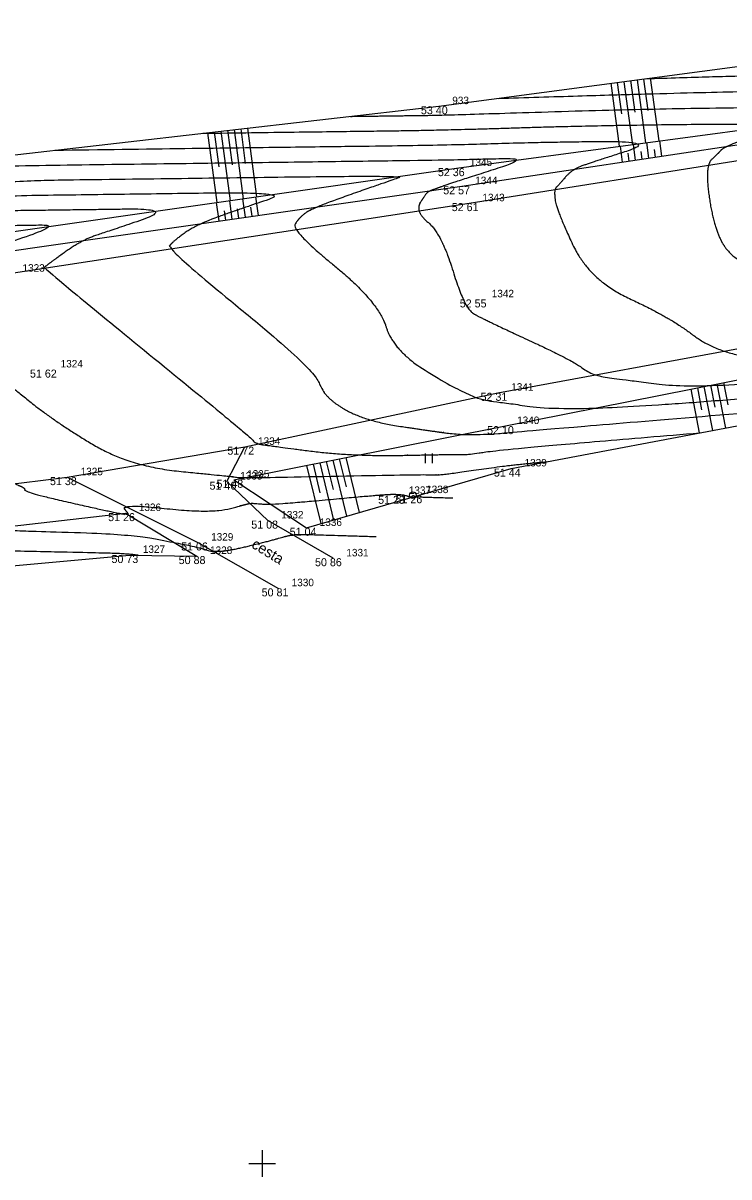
# Model space of a CAD drawing. Extents: x -704017 to -701500, y -1008977 to -1008450.
# Drawn here: x -703008.96 to -702982.5, y -1008850.5 to -1008807.25 of the extents above; entities that cross this region are included whole.
import ezdxf

# ---------------------------------------------------------------- set-up
doc = ezdxf.new("R2010")
doc.units = 0
for name, color, linetype in [('Z_body', 7, 'Continuous'), ('Z_body_cisla', 7, 'Continuous'), ('Z_body_vysky', 7, 'Continuous'), ('Z_cesty', 7, 'Continuous'), ('Z_hekt_sit', 7, 'Continuous'), ('Z_komunikace', 7, 'Continuous'), ('Z_popis', 7, 'Continuous'), ('Z_sloupky', 7, 'Continuous'), ('Z_teren_hrany_paty', 7, 'Continuous'), ('Z_vrstevnice_hlavni', 7, 'Continuous'), ('Z_vrstevnice_vedlejsi', 7, 'Continuous')]:
    doc.layers.add(name, color=color, linetype=linetype)

# ---------------------------------------------------------------- blocks, each defined once
blk = doc.blocks.new('POINT_DISPLAY')
blk.add_line((0, 0), (0, 0))
blk = doc.blocks.new('Z306')
for p, q in [((-0.13, 0.17), (-0.13, -0.2)), ((0.13, 0.17), (0.13, -0.2))]:
    blk.add_line(p, q)
blk = doc.blocks.new('Z15')
blk.add_circle((0, 0), 0.125)

msp = doc.modelspace()

# ---------------------------------------------------------------- linework, layer by layer
at = {"layer": 'Z_cesty'}
for p, q in [((-703001.32, -1008824.44), (-703000.65, -1008823.13)), ((-703007.3, -1008824.27), (-703002.41, -1008826.72)), ((-702999.78, -1008825.9), (-703001.32, -1008824.44)), ((-702997.34, -1008827.31), (-702999.78, -1008825.9)), ((-703002.41, -1008826.72), (-702999.39, -1008828.44))]:
    msp.add_line(p, q, dxfattribs=at)
at = {"layer": 'Z_hekt_sit'}
for p, q in [((-703000, -1008849.5), (-703000, -1008850.5)), ((-703000.5, -1008850), (-702999.5, -1008850))]:
    msp.add_line(p, q, dxfattribs=at)
at = {"layer": 'Z_komunikace'}
for p, q in [((-702992.24, -1008814), (-702978.18, -1008811.77)), ((-703009.48, -1008816.64), (-702992.24, -1008814)), ((-702991.16, -1008821.11), (-702976.85, -1008818.47)), ((-703000.65, -1008823.13), (-702991.16, -1008821.11)), ((-703007.3, -1008824.27), (-703000.65, -1008823.13)), ((-703026.19, -1008826.6), (-703007.3, -1008824.27))]:
    msp.add_line(p, q, dxfattribs=at)
at = {"layer": 'Z_teren_hrany_paty'}
for p, q in [((-702993.37, -1008810.37), (-702978.74, -1008808.42)), ((-702986.93, -1008809.51), (-702986.62, -1008811.87)), ((-702986.69, -1008809.48), (-702986.53, -1008810.66)), ((-702986.44, -1008809.45), (-702986.12, -1008811.81)), ((-702986.19, -1008809.41), (-702986.03, -1008810.59)), ((-702985.94, -1008809.38), (-702985.63, -1008811.74)), ((-702985.7, -1008809.35), (-702985.54, -1008810.53)), ((-702985.45, -1008809.31), (-702985.13, -1008811.67)), ((-703012.19, -1008812.52), (-702993.37, -1008810.37)), ((-702992.71, -1008812.69), (-702978.64, -1008810.8)), ((-703002.04, -1008811.36), (-703001.7, -1008813.98)), ((-703001.79, -1008811.33), (-703001.62, -1008812.64)), ((-703001.54, -1008811.3), (-703001.2, -1008813.91)), ((-703001.29, -1008811.27), (-703001.12, -1008812.57)), ((-703001.04, -1008811.25), (-703000.71, -1008813.84)), ((-703000.79, -1008811.22), (-703000.63, -1008812.51)), ((-703000.55, -1008811.19), (-703000.21, -1008813.77)), ((-702992.51, -1008813.37), (-702978.59, -1008811.28)), ((-702986, -1008812.39), (-702986.08, -1008811.8)), ((-702985.5, -1008812.32), (-702985.58, -1008811.73)), ((-702985.01, -1008812.24), (-702985.09, -1008811.67)), ((-702986.49, -1008812.47), (-702986.57, -1008811.87)), ((-702986.24, -1008812.43), (-702986.28, -1008812.13)), ((-702985.75, -1008812.35), (-702985.79, -1008812.06)), ((-702985.25, -1008812.28), (-702985.29, -1008811.99)), ((-703010.43, -1008815.23), (-702992.71, -1008812.69)), ((-703010.28, -1008815.91), (-702992.51, -1008813.37)), ((-703001.61, -1008814.67), (-703001.71, -1008813.98)), ((-703001.12, -1008814.6), (-703001.21, -1008813.91)), ((-703000.62, -1008814.53), (-703000.72, -1008813.84)), ((-703000.13, -1008814.46), (-703000.23, -1008813.77)), ((-703001.36, -1008814.64), (-703001.41, -1008814.29)), ((-703000.87, -1008814.56), (-703000.92, -1008814.22)), ((-703000.37, -1008814.49), (-703000.42, -1008814.15)), ((-702990.94, -1008822.36), (-702976.73, -1008819.55)), ((-702983.44, -1008820.88), (-702983.12, -1008822.52)), ((-702983.19, -1008820.83), (-702983.03, -1008821.65)), ((-702982.95, -1008820.78), (-702982.63, -1008822.43)), ((-702982.7, -1008820.73), (-702982.54, -1008821.56)), ((-702990.66, -1008823.95), (-702976.53, -1008821.27)), ((-702983.93, -1008820.97), (-702983.61, -1008822.61)), ((-702983.68, -1008820.93), (-702983.53, -1008821.75)), ((-703001.06, -1008824.37), (-702990.94, -1008822.36)), ((-702998.33, -1008823.83), (-702997.8, -1008826.01)), ((-702998.09, -1008823.78), (-702997.83, -1008824.86)), ((-702997.84, -1008823.73), (-702997.32, -1008825.88)), ((-702997.6, -1008823.68), (-702997.34, -1008824.74)), ((-702997.35, -1008823.63), (-702996.84, -1008825.74)), ((-702997.11, -1008823.58), (-702996.85, -1008824.63)), ((-702996.86, -1008823.54), (-702996.36, -1008825.6)), ((-703001.06, -1008824.37), (-702998.34, -1008826.17)), ((-702998.34, -1008826.17), (-702990.66, -1008823.95)), ((-703013.93, -1008826.64), (-703005.12, -1008825.62)), ((-703005.12, -1008825.62), (-703002.45, -1008827.23)), ((-703014.43, -1008828.07), (-703004.97, -1008827.19)), ((-703004.97, -1008827.19), (-703002.45, -1008827.23))]:
    msp.add_line(p, q, dxfattribs=at)
at = {"layer": 'Z_vrstevnice_hlavni'}
for points in [[(-703002.226, -1008811.382), (-702996.667, -1008811.309), (-702993.116, -1008811.262), (-702987.451, -1008811.082), (-702980.203, -1008811.01), (-702980.816, -1008811.203), (-702982.698, -1008811.897), (-702982.901, -1008812.139), (-702983.396, -1008812.597), (-702983.113, -1008814.73), (-702982.519, -1008815.989), (-702981.087, -1008816.648), (-702978.337, -1008818.744), (-702976.797, -1008818.95), (-702976.17, -1008819.445), (-702974.047, -1008819.074), (-702962.753, -1008817.952), (-702949.418, -1008816.602)], [(-703019.06, -1008814.604), (-703017.54, -1008814.633), (-703015.28, -1008814.438), (-703011.397, -1008813.742), (-703004.908, -1008813.657), (-702998.903, -1008813.578), (-703000.519, -1008814.121), (-703002.44, -1008814.789), (-703003.378, -1008815.464), (-703003.548, -1008815.732), (-702998.004, -1008820.258), (-702997.695, -1008821.268), (-702996.146, -1008822.171), (-702993.495, -1008822.563), (-702992.572, -1008822.684), (-702991.407, -1008822.66), (-702991.346, -1008822.668), (-702990.898, -1008822.601), (-702977.897, -1008821.529)], [(-703029.983, -1008816.493), (-703028.21, -1008816.668), (-703028.152, -1008816.583), (-703021.097, -1008816.739), (-703014.765, -1008816.068), (-703015.559, -1008816.38), (-703017.455, -1008817.22), (-703017.727, -1008817.416), (-703018.217, -1008817.971), (-703018.119, -1008819.778), (-703016.98, -1008821.504), (-703015.806, -1008822.959), (-703013.232, -1008825.002), (-703011.963, -1008825.402), (-703011.966, -1008825.938), (-703010.574, -1008826.251), (-703005.046, -1008826.39), (-703003.293, -1008826.722), (-703002.423, -1008826.89), (-703001.685, -1008827.133), (-702999.664, -1008826.653), (-702998.893, -1008826.413), (-702998.118, -1008826.423), (-702995.728, -1008826.499)]]:
    msp.add_open_spline(points, degree=2, dxfattribs=at)
at = {"layer": 'Z_vrstevnice_vedlejsi'}
for points in [[(-702985.612, -1008809.336), (-702981.287, -1008809.199), (-702978.708, -1008809.173), (-702968.75, -1008808.243), (-702962.298, -1008807.683), (-702957.995, -1008807.147), (-702959.147, -1008807.518), (-702962.846, -1008808.642), (-702963.072, -1008808.701), (-702963.112, -1008808.715), (-702963.129, -1008808.728), (-702963.815, -1008809.151), (-702964.114, -1008812.273), (-702964.054, -1008812.725), (-702963.539, -1008813.003), (-702961.465, -1008813.922), (-702958.604, -1008815.239), (-702957.47, -1008815.285), (-702953.814, -1008815.444), (-702945.32, -1008814.568), (-702935.231, -1008813.695)], [(-702991.153, -1008810.075), (-702983.342, -1008809.827), (-702978.683, -1008809.78), (-702965.191, -1008808.52), (-702968.881, -1008809.484), (-702969.9, -1008809.84), (-702970.365, -1008810.191), (-702970.721, -1008810.41), (-702970.877, -1008812.031), (-702970.629, -1008813.896), (-702968.506, -1008815.043), (-702965.314, -1008816.457), (-702967.254, -1008817.299), (-702960.901, -1008816.678), (-702960.627, -1008816.69), (-702945.699, -1008815.149), (-702939.678, -1008814.629)], [(-702996.691, -1008810.749), (-702994.606, -1008810.722), (-702993.275, -1008810.705), (-702985.396, -1008810.455), (-702978.657, -1008810.387), (-702973.197, -1008809.877), (-702974.69, -1008810.268), (-702976.689, -1008810.965), (-702977.601, -1008811.653), (-702977.628, -1008811.669), (-702977.639, -1008811.789), (-702977.204, -1008815.066), (-702973.473, -1008817.083), (-702972.181, -1008817.655), (-702975.1, -1008818.923), (-702974.772, -1008819.183), (-702967.339, -1008817.883), (-702961.807, -1008817.334), (-702951.14, -1008816.253), (-702946.078, -1008815.731), (-702944.125, -1008815.562)], [(-703007.762, -1008812.014), (-702998.727, -1008811.896), (-702992.958, -1008811.82), (-702989.505, -1008811.71), (-702985.089, -1008811.666), (-702987.615, -1008812.463), (-702988.402, -1008812.753), (-702988.887, -1008813.332), (-702989.065, -1008813.496), (-702988.964, -1008814.262), (-702987.725, -1008816.889), (-702984.737, -1008818.264), (-702982.983, -1008819.601), (-702980.399, -1008819.947), (-702979.394, -1008820.077), (-702976.694, -1008819.857), (-702973.588, -1008819.553), (-702963.698, -1008818.571), (-702955.492, -1008817.739)], [(-703012.868, -1008812.766), (-703012.118, -1008812.631), (-703000.787, -1008812.483), (-702992.799, -1008812.378), (-702991.56, -1008812.338), (-702989.974, -1008812.323), (-702992.577, -1008813.143), (-702993.73, -1008813.544), (-702993.845, -1008813.627), (-702994.279, -1008814.312), (-702993.279, -1008815.128), (-702992.418, -1008817.943), (-702991.738, -1008818.339), (-702988.386, -1008819.881), (-702987.629, -1008820.459), (-702986.513, -1008820.608), (-702983.835, -1008820.955), (-702976.635, -1008820.369), (-702968.352, -1008819.557), (-702964.643, -1008819.189), (-702961.566, -1008818.877)], [(-703016.258, -1008813.994), (-703011.757, -1008813.186), (-703002.848, -1008813.07), (-702994.602, -1008812.961), (-702995.096, -1008813.127), (-702998.085, -1008814.167), (-702998.612, -1008814.546), (-702998.914, -1008815.022), (-702995.642, -1008817.693), (-702995.056, -1008819.605), (-702992.125, -1008821.315), (-702991.097, -1008821.467), (-702988.276, -1008821.833), (-702976.575, -1008820.881), (-702969.113, -1008820.15)], [(-703021.752, -1008815.097), (-703018.422, -1008815.16), (-703013.47, -1008814.734), (-703011.036, -1008814.297), (-703006.969, -1008814.244), (-703003.204, -1008814.194), (-703005.942, -1008815.115), (-703006.796, -1008815.412), (-703008.145, -1008816.383), (-703008.182, -1008816.441), (-703000.367, -1008822.822), (-703000.333, -1008822.93), (-703000.167, -1008823.027), (-702999.883, -1008823.069), (-702996.653, -1008823.495), (-702992.573, -1008823.41), (-702992.361, -1008823.439), (-702990.792, -1008823.203), (-702983.595, -1008822.61)], [(-703024.443, -1008815.59), (-703019.303, -1008815.687), (-703011.661, -1008815.029), (-703010.675, -1008814.852), (-703009.029, -1008814.831), (-703007.505, -1008814.811), (-703010.314, -1008815.755), (-703010.932, -1008816.029), (-703010.957, -1008816.047), (-703011.793, -1008816.992), (-703011.767, -1008817.471), (-703009.778, -1008820.485), (-703009.551, -1008820.766), (-703007.675, -1008822.255), (-703004.953, -1008823.868), (-703001.217, -1008824.238), (-703001.026, -1008824.267), (-703000.734, -1008824.305), (-702993.74, -1008824.16), (-702993.376, -1008824.21), (-702990.685, -1008823.805), (-702989.293, -1008823.691)], [(-703027.134, -1008816.083), (-703020.184, -1008816.214), (-703013.08, -1008815.603), (-703011.481, -1008815.433), (-703011.673, -1008815.509), (-703014.194, -1008816.625), (-703014.342, -1008816.731), (-703015.005, -1008817.481), (-703014.943, -1008818.624), (-703013.379, -1008820.994), (-703012.679, -1008821.863), (-703009.33, -1008824.52), (-703008.895, -1008824.657), (-703008.896, -1008824.841), (-703005.33, -1008825.644), (-703005.117, -1008825.65), (-703005.05, -1008825.662), (-703004.985, -1008825.675), (-703005.313, -1008825.265), (-703001.892, -1008825.637), (-703000.469, -1008825.247), (-703000.324, -1008825.25), (-702999.638, -1008825.311), (-702995.485, -1008824.922), (-702994.907, -1008824.91), (-702994.567, -1008824.957), (-702994.531, -1008825.005), (-702994.308, -1008825.005), (-702992.848, -1008825.051)], [(-703032.938, -1008816.847), (-703028.21, -1008817.315), (-703028.056, -1008817.087), (-703022.782, -1008817.204), (-703018.049, -1008816.702), (-703019.444, -1008817.252), (-703020.717, -1008817.815), (-703021.112, -1008818.1), (-703021.429, -1008818.46), (-703021.294, -1008820.932), (-703020.581, -1008822.014), (-703018.934, -1008824.056), (-703017.135, -1008825.483), (-703015.03, -1008826.147), (-703015.033, -1008826.759), (-703014.032, -1008826.932), (-703006.599, -1008827.09), (-703004.976, -1008827.131), (-703004.634, -1008827.195)]]:
    msp.add_open_spline(points, degree=2, dxfattribs=at)

# ---------------------------------------------------------------- block references
at = {"layer": 'Z_body'}
for p in [(-702993.37, -1008810.37), (-702992.71, -1008812.69), (-702992.51, -1008813.37), (-702992.24, -1008814), (-702991.89, -1008817.61), (-703008.05, -1008820.24), (-702991.16, -1008821.11), (-702990.94, -1008822.36), (-703000.65, -1008823.13), (-703007.3, -1008824.27), (-703001.06, -1008824.37), (-702990.66, -1008823.95), (-703001.32, -1008824.44), (-702995, -1008824.97), (-702994.35, -1008824.95), (-703005.12, -1008825.62), (-702999.78, -1008825.9), (-702998.34, -1008826.17), (-703002.41, -1008826.72), (-703004.97, -1008827.19), (-703002.45, -1008827.23), (-702997.34, -1008827.31), (-702999.39, -1008828.44)]:
    msp.add_blockref('POINT_DISPLAY', p, dxfattribs=at)
at = {"layer": 'Z_popis'}
msp.add_blockref('Z306', (-702993.76, -1008823.55), dxfattribs=at)
at = {"layer": 'Z_sloupky'}
msp.add_blockref('Z15', (-702994.35, -1008824.95), dxfattribs=at)

# ---------------------------------------------------------------- texts
at = {"layer": 'Z_body_cisla'}
for s, p in [('933', (-702992.87, -1008810.29)), ('1345', (-702992.21, -1008812.61)), ('1344', (-702992.01, -1008813.29)), ('1343', (-702991.74, -1008813.93)), ('1323', (-703008.98, -1008816.57)), ('1342', (-702991.39, -1008817.53)), ('1324', (-703007.55, -1008820.16)), ('1341', (-702990.66, -1008821.03)), ('1340', (-702990.44, -1008822.28)), ('1334', (-703000.15, -1008823.06)), ('1325', (-703006.8, -1008824.2)), ('1339', (-702990.16, -1008823.87)), ('1333', (-703000.82, -1008824.36)), ('1335', (-703000.56, -1008824.29)), ('1337', (-702994.5, -1008824.9)), ('1338', (-702993.85, -1008824.87)), ('1326', (-703004.62, -1008825.54)), ('1332', (-702999.28, -1008825.82)), ('1336', (-702997.84, -1008826.1)), ('1329', (-703001.91, -1008826.65)), ('1327', (-703004.47, -1008827.11)), ('1328', (-703001.95, -1008827.15)), ('1331', (-702996.84, -1008827.24)), ('1330', (-702998.89, -1008828.36))]:
    msp.add_text(s, height=0.28, dxfattribs=at).set_placement(p)
at = {"layer": 'Z_body_vysky'}
for s, p in [('53 40', (-702994.045, -1008810.67)), ('52 36', (-702993.41, -1008812.99)), ('52 57', (-702993.21, -1008813.67)), ('52 61', (-702992.89, -1008814.3)), ('52 55', (-702992.59, -1008817.91)), ('51 62', (-703008.7, -1008820.54)), ('52 31', (-702991.81, -1008821.41)), ('52 10', (-702991.565, -1008822.66)), ('51 72', (-703001.3, -1008823.43)), ('51 38', (-703007.95, -1008824.57)), ('51 48', (-703001.71, -1008824.67)), ('51 44', (-702991.31, -1008824.25)), ('51 46', (-703001.97, -1008824.74)), ('51 23', (-702995.65, -1008825.27)), ('51 26', (-702995, -1008825.25)), ('51 26', (-703005.77, -1008825.92)), ('51 08', (-703000.405, -1008826.2)), ('51 04', (-702998.965, -1008826.47)), ('51 06', (-703003.035, -1008827.02)), ('50 73', (-703005.645, -1008827.49)), ('50 88', (-703003.125, -1008827.53)), ('50 86', (-702998.015, -1008827.61)), ('50 81', (-703000.015, -1008828.74))]:
    msp.add_text(s, height=0.3, dxfattribs=at).set_placement(p)
at = {"layer": 'Z_popis'}
msp.add_text('cesta', height=0.4, rotation=328.5, dxfattribs=at).set_placement((-703000.43, -1008826.89))

doc.saveas('drawing.dxf')
